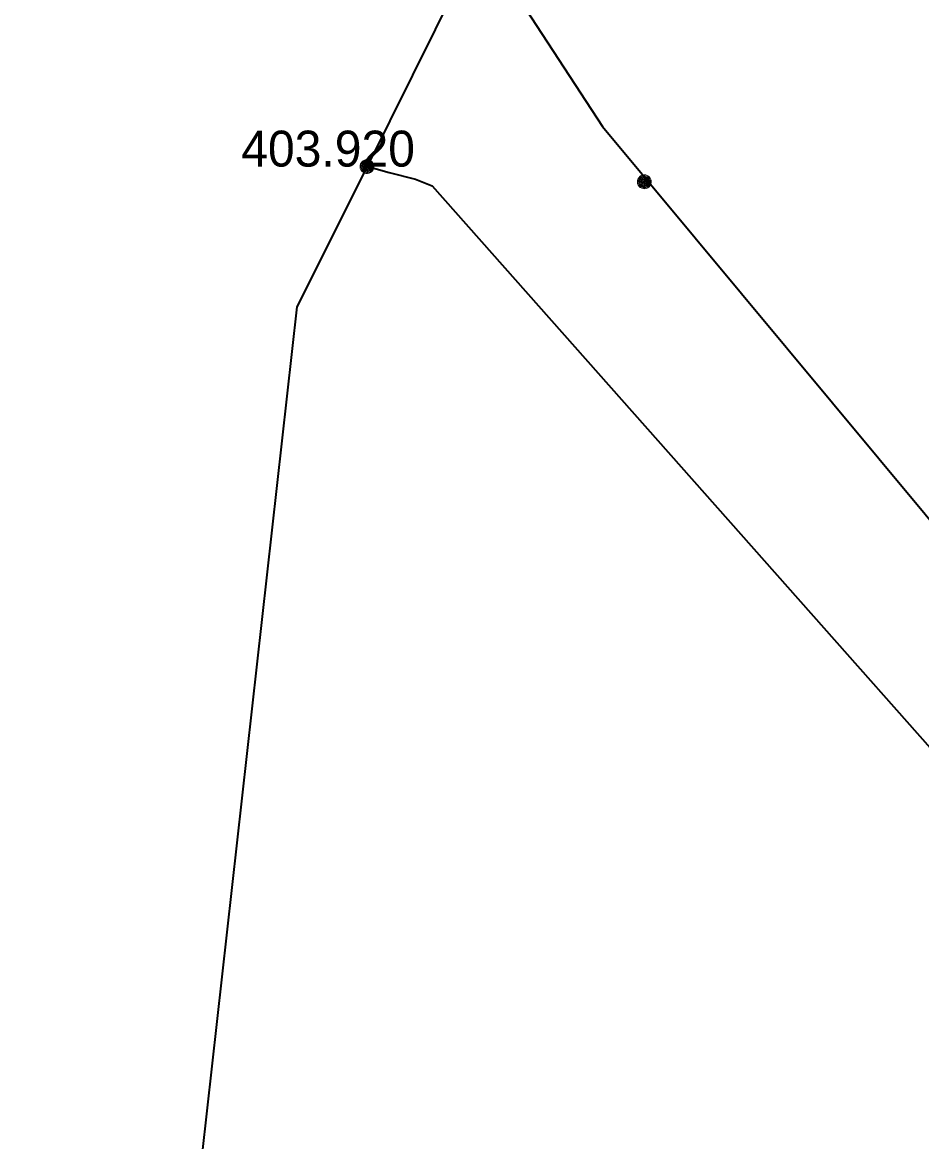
# Model space of a CAD drawing. Extents: x -873619 to -867639, y -1015082 to -1012326.
# Drawn here: x -867986.12 to -867956.09, y -1012758.26 to -1012720.88 of the extents above; entities that cross this region are included whole.
import ezdxf

# ---------------------------------------------------------------- set-up
doc = ezdxf.new("R2010")
doc.units = 0
doc.header["$LTSCALE"] = 0.44
for name, color, linetype, lineweight in [('1', 7, 'Continuous', 13), ('12', 7, 'Continuous', 13), ('21', 7, 'Continuous', 35), ('32', 7, 'Continuous', 13)]:
    doc.layers.add(name, color=color, linetype=linetype, lineweight=lineweight)

msp = doc.modelspace()

# ---------------------------------------------------------------- linework, layer by layer
at = {"layer": '1', "lineweight": 35}
for points in [[(-867928.158, -1012682.175), (-867928.532, -1012682.575), (-867928.834, -1012682.846), (-867929.235, -1012683.248), (-867941.259, -1012695.377), (-867959.972, -1012709.533), (-867967.543, -1012714.627), (-867970.064, -1012716.534), (-867974.611, -1012725.697)], [(-867974.611, -1012725.697), (-867976.949, -1012730.385), (-867980.624, -1012763.205), (-867983.112, -1012775.195), (-867978.719, -1012795.525), (-867979.823, -1012805.464), (-867997.768, -1012829.005), (-868011.042, -1012836.499), (-868058.95, -1012844.4), (-868077.43, -1012833.46), (-868085.171, -1012827.86)], [(-867974.611, -1012725.697), (-867974.301, -1012725.775), (-867973.868, -1012725.89), (-867972.988, -1012726.12), (-867972.44, -1012726.34), (-867942.73, -1012759.87), (-867932.66, -1012771.332), (-867928.969, -1012774.977), (-867916.529, -1012789.697), (-867904.95, -1012804.27)]]:
    msp.add_lwpolyline(points, dxfattribs=at)
at = {"layer": '1'}
for points in [[(-867974.38, -1012725.697), (-867974.386, -1012725.645), (-867974.403, -1012725.595), (-867974.432, -1012725.551), (-867974.469, -1012725.514), (-867974.514, -1012725.487), (-867974.564, -1012725.47), (-867974.617, -1012725.466), (-867974.669, -1012725.473), (-867974.718, -1012725.492), (-867974.761, -1012725.521), (-867974.797, -1012725.56), (-867974.823, -1012725.605), (-867974.839, -1012725.656), (-867974.842, -1012725.708), (-867974.834, -1012725.76), (-867974.814, -1012725.809), (-867974.783, -1012725.852), (-867974.744, -1012725.886), (-867974.698, -1012725.912), (-867974.647, -1012725.926), (-867974.594, -1012725.928), (-867974.543, -1012725.918), (-867974.495, -1012725.897), (-867974.452, -1012725.866), (-867974.418, -1012725.825), (-867974.394, -1012725.779), (-867974.382, -1012725.728)], [(-867974.41, -1012725.697), (-867974.416, -1012725.648), (-867974.433, -1012725.602), (-867974.461, -1012725.562), (-867974.498, -1012725.53), (-867974.542, -1012725.508), (-867974.59, -1012725.497), (-867974.639, -1012725.497), (-867974.686, -1012725.51), (-867974.729, -1012725.534), (-867974.765, -1012725.567), (-867974.792, -1012725.608), (-867974.808, -1012725.655), (-867974.812, -1012725.704), (-867974.805, -1012725.752), (-867974.786, -1012725.797), (-867974.756, -1012725.837), (-867974.718, -1012725.868), (-867974.674, -1012725.888), (-867974.626, -1012725.898), (-867974.577, -1012725.896), (-867974.53, -1012725.881), (-867974.487, -1012725.856), (-867974.453, -1012725.822), (-867974.427, -1012725.78), (-867974.413, -1012725.733)], [(-867974.44, -1012725.697), (-867974.446, -1012725.652), (-867974.463, -1012725.61), (-867974.491, -1012725.575), (-867974.527, -1012725.548), (-867974.569, -1012725.531), (-867974.614, -1012725.526), (-867974.659, -1012725.532), (-867974.7, -1012725.551), (-867974.735, -1012725.579), (-867974.762, -1012725.616), (-867974.778, -1012725.658), (-867974.782, -1012725.703), (-867974.775, -1012725.748), (-867974.756, -1012725.789), (-867974.727, -1012725.823), (-867974.69, -1012725.849), (-867974.647, -1012725.865), (-867974.602, -1012725.868), (-867974.557, -1012725.86), (-867974.517, -1012725.84), (-867974.483, -1012725.811), (-867974.457, -1012725.773), (-867974.443, -1012725.73)], [(-867974.47, -1012725.697), (-867974.475, -1012725.656), (-867974.493, -1012725.619), (-867974.52, -1012725.588), (-867974.555, -1012725.567), (-867974.595, -1012725.556), (-867974.636, -1012725.558), (-867974.675, -1012725.571), (-867974.709, -1012725.595), (-867974.734, -1012725.627), (-867974.749, -1012725.665), (-867974.752, -1012725.706), (-867974.744, -1012725.746), (-867974.724, -1012725.782), (-867974.695, -1012725.811), (-867974.658, -1012725.83), (-867974.618, -1012725.838), (-867974.577, -1012725.834), (-867974.539, -1012725.819), (-867974.507, -1012725.793), (-867974.484, -1012725.759), (-867974.471, -1012725.72)], [(-867974.5, -1012725.697), (-867974.505, -1012725.661), (-867974.523, -1012725.629), (-867974.549, -1012725.604), (-867974.583, -1012725.589), (-867974.619, -1012725.586), (-867974.654, -1012725.594), (-867974.685, -1012725.614), (-867974.708, -1012725.642), (-867974.721, -1012725.676), (-867974.721, -1012725.713), (-867974.71, -1012725.748), (-867974.689, -1012725.777), (-867974.659, -1012725.798), (-867974.624, -1012725.808), (-867974.587, -1012725.806), (-867974.553, -1012725.792), (-867974.526, -1012725.769), (-867974.507, -1012725.737), (-867974.5, -1012725.702)], [(-867974.53, -1012725.697), (-867974.535, -1012725.666), (-867974.552, -1012725.64), (-867974.578, -1012725.623), (-867974.608, -1012725.616), (-867974.639, -1012725.62), (-867974.666, -1012725.637), (-867974.684, -1012725.661), (-867974.692, -1012725.692), (-867974.688, -1012725.722), (-867974.673, -1012725.75), (-867974.649, -1012725.769), (-867974.619, -1012725.778), (-867974.588, -1012725.775), (-867974.56, -1012725.761), (-867974.54, -1012725.737), (-867974.53, -1012725.708)], [(-867974.56, -1012725.697), (-867974.565, -1012725.673), (-867974.582, -1012725.655), (-867974.605, -1012725.646), (-867974.629, -1012725.649), (-867974.65, -1012725.663), (-867974.661, -1012725.685), (-867974.661, -1012725.71), (-867974.649, -1012725.731), (-867974.629, -1012725.745), (-867974.604, -1012725.748), (-867974.581, -1012725.739), (-867974.565, -1012725.721)], [(-867974.59, -1012725.697), (-867974.595, -1012725.682), (-867974.61, -1012725.676), (-867974.625, -1012725.68), (-867974.632, -1012725.694), (-867974.628, -1012725.709), (-867974.615, -1012725.718), (-867974.6, -1012725.715), (-867974.59, -1012725.703)]]:
    msp.add_lwpolyline(points, close=True, dxfattribs=at)
at = {"layer": '12'}
for points in [[(-867974.38, -1012725.697), (-867974.386, -1012725.645), (-867974.403, -1012725.595), (-867974.432, -1012725.551), (-867974.469, -1012725.514), (-867974.514, -1012725.487), (-867974.564, -1012725.47), (-867974.617, -1012725.466), (-867974.669, -1012725.473), (-867974.718, -1012725.492), (-867974.761, -1012725.521), (-867974.797, -1012725.56), (-867974.823, -1012725.605), (-867974.839, -1012725.656), (-867974.842, -1012725.708), (-867974.834, -1012725.76), (-867974.814, -1012725.809), (-867974.783, -1012725.852), (-867974.744, -1012725.886), (-867974.698, -1012725.912), (-867974.647, -1012725.926), (-867974.594, -1012725.928), (-867974.543, -1012725.918), (-867974.495, -1012725.897), (-867974.452, -1012725.866), (-867974.418, -1012725.825), (-867974.394, -1012725.779), (-867974.382, -1012725.728)], [(-867974.41, -1012725.697), (-867974.416, -1012725.648), (-867974.433, -1012725.602), (-867974.461, -1012725.562), (-867974.498, -1012725.53), (-867974.542, -1012725.508), (-867974.59, -1012725.497), (-867974.639, -1012725.497), (-867974.686, -1012725.51), (-867974.729, -1012725.534), (-867974.765, -1012725.567), (-867974.792, -1012725.608), (-867974.808, -1012725.655), (-867974.812, -1012725.704), (-867974.805, -1012725.752), (-867974.786, -1012725.797), (-867974.756, -1012725.837), (-867974.718, -1012725.868), (-867974.674, -1012725.888), (-867974.626, -1012725.898), (-867974.577, -1012725.896), (-867974.53, -1012725.881), (-867974.487, -1012725.856), (-867974.453, -1012725.822), (-867974.427, -1012725.78), (-867974.413, -1012725.733)], [(-867974.44, -1012725.697), (-867974.446, -1012725.652), (-867974.463, -1012725.61), (-867974.491, -1012725.575), (-867974.527, -1012725.548), (-867974.569, -1012725.531), (-867974.614, -1012725.526), (-867974.659, -1012725.532), (-867974.7, -1012725.551), (-867974.735, -1012725.579), (-867974.762, -1012725.616), (-867974.778, -1012725.658), (-867974.782, -1012725.703), (-867974.775, -1012725.748), (-867974.756, -1012725.789), (-867974.727, -1012725.823), (-867974.69, -1012725.849), (-867974.647, -1012725.865), (-867974.602, -1012725.868), (-867974.557, -1012725.86), (-867974.517, -1012725.84), (-867974.483, -1012725.811), (-867974.457, -1012725.773), (-867974.443, -1012725.73)], [(-867974.47, -1012725.697), (-867974.475, -1012725.656), (-867974.493, -1012725.619), (-867974.52, -1012725.588), (-867974.555, -1012725.567), (-867974.595, -1012725.556), (-867974.636, -1012725.558), (-867974.675, -1012725.571), (-867974.709, -1012725.595), (-867974.734, -1012725.627), (-867974.749, -1012725.665), (-867974.752, -1012725.706), (-867974.744, -1012725.746), (-867974.724, -1012725.782), (-867974.695, -1012725.811), (-867974.658, -1012725.83), (-867974.618, -1012725.838), (-867974.577, -1012725.834), (-867974.539, -1012725.819), (-867974.507, -1012725.793), (-867974.484, -1012725.759), (-867974.471, -1012725.72)], [(-867974.5, -1012725.697), (-867974.505, -1012725.661), (-867974.523, -1012725.629), (-867974.549, -1012725.604), (-867974.583, -1012725.589), (-867974.619, -1012725.586), (-867974.654, -1012725.594), (-867974.685, -1012725.614), (-867974.708, -1012725.642), (-867974.721, -1012725.676), (-867974.721, -1012725.713), (-867974.71, -1012725.748), (-867974.689, -1012725.777), (-867974.659, -1012725.798), (-867974.624, -1012725.808), (-867974.587, -1012725.806), (-867974.553, -1012725.792), (-867974.526, -1012725.769), (-867974.507, -1012725.737), (-867974.5, -1012725.702)], [(-867974.53, -1012725.697), (-867974.535, -1012725.666), (-867974.552, -1012725.64), (-867974.578, -1012725.623), (-867974.608, -1012725.616), (-867974.639, -1012725.62), (-867974.666, -1012725.637), (-867974.684, -1012725.661), (-867974.692, -1012725.692), (-867974.688, -1012725.722), (-867974.673, -1012725.75), (-867974.649, -1012725.769), (-867974.619, -1012725.778), (-867974.588, -1012725.775), (-867974.56, -1012725.761), (-867974.54, -1012725.737), (-867974.53, -1012725.708)], [(-867974.56, -1012725.697), (-867974.565, -1012725.673), (-867974.582, -1012725.655), (-867974.605, -1012725.646), (-867974.629, -1012725.649), (-867974.65, -1012725.663), (-867974.661, -1012725.685), (-867974.661, -1012725.71), (-867974.649, -1012725.731), (-867974.629, -1012725.745), (-867974.604, -1012725.748), (-867974.581, -1012725.739), (-867974.565, -1012725.721)], [(-867974.59, -1012725.697), (-867974.595, -1012725.682), (-867974.61, -1012725.676), (-867974.625, -1012725.68), (-867974.632, -1012725.694), (-867974.628, -1012725.709), (-867974.615, -1012725.718), (-867974.6, -1012725.715), (-867974.59, -1012725.703)]]:
    msp.add_lwpolyline(points, close=True, dxfattribs=at)
at = {"layer": '21'}
msp.add_lwpolyline([(-867981.801, -1012701.313), (-867966.749, -1012724.362), (-867954.427, -1012739.171)], dxfattribs=at)
at = {"layer": '32'}
for points in [[(-867965.12, -1012726.205), (-867965.126, -1012726.153), (-867965.143, -1012726.103), (-867965.172, -1012726.059), (-867965.209, -1012726.022), (-867965.254, -1012725.995), (-867965.304, -1012725.978), (-867965.357, -1012725.974), (-867965.409, -1012725.981), (-867965.458, -1012726), (-867965.501, -1012726.029), (-867965.537, -1012726.068), (-867965.563, -1012726.113), (-867965.579, -1012726.164), (-867965.582, -1012726.216), (-867965.574, -1012726.268), (-867965.554, -1012726.317), (-867965.523, -1012726.36), (-867965.484, -1012726.394), (-867965.438, -1012726.42), (-867965.387, -1012726.434), (-867965.334, -1012726.436), (-867965.283, -1012726.426), (-867965.235, -1012726.405), (-867965.192, -1012726.374), (-867965.158, -1012726.333), (-867965.134, -1012726.287), (-867965.122, -1012726.236)], [(-867965.15, -1012726.205), (-867965.156, -1012726.156), (-867965.173, -1012726.11), (-867965.201, -1012726.07), (-867965.238, -1012726.038), (-867965.282, -1012726.016), (-867965.33, -1012726.005), (-867965.379, -1012726.005), (-867965.426, -1012726.018), (-867965.469, -1012726.042), (-867965.505, -1012726.075), (-867965.532, -1012726.116), (-867965.548, -1012726.163), (-867965.552, -1012726.212), (-867965.545, -1012726.26), (-867965.526, -1012726.305), (-867965.496, -1012726.345), (-867965.458, -1012726.376), (-867965.414, -1012726.396), (-867965.366, -1012726.406), (-867965.317, -1012726.404), (-867965.27, -1012726.389), (-867965.227, -1012726.364), (-867965.193, -1012726.33), (-867965.167, -1012726.288), (-867965.153, -1012726.241)], [(-867965.18, -1012726.205), (-867965.186, -1012726.16), (-867965.203, -1012726.118), (-867965.231, -1012726.083), (-867965.267, -1012726.056), (-867965.309, -1012726.039), (-867965.354, -1012726.034), (-867965.399, -1012726.04), (-867965.44, -1012726.059), (-867965.475, -1012726.087), (-867965.502, -1012726.124), (-867965.518, -1012726.166), (-867965.522, -1012726.211), (-867965.515, -1012726.256), (-867965.496, -1012726.297), (-867965.467, -1012726.331), (-867965.43, -1012726.357), (-867965.387, -1012726.373), (-867965.342, -1012726.376), (-867965.297, -1012726.368), (-867965.257, -1012726.348), (-867965.223, -1012726.319), (-867965.197, -1012726.281), (-867965.183, -1012726.238)], [(-867965.21, -1012726.205), (-867965.215, -1012726.164), (-867965.233, -1012726.127), (-867965.26, -1012726.096), (-867965.295, -1012726.075), (-867965.335, -1012726.064), (-867965.376, -1012726.066), (-867965.415, -1012726.079), (-867965.449, -1012726.103), (-867965.474, -1012726.135), (-867965.489, -1012726.173), (-867965.492, -1012726.214), (-867965.484, -1012726.254), (-867965.464, -1012726.29), (-867965.435, -1012726.319), (-867965.398, -1012726.338), (-867965.358, -1012726.346), (-867965.317, -1012726.342), (-867965.279, -1012726.327), (-867965.247, -1012726.301), (-867965.224, -1012726.267), (-867965.211, -1012726.228)], [(-867965.24, -1012726.205), (-867965.245, -1012726.169), (-867965.263, -1012726.137), (-867965.289, -1012726.112), (-867965.323, -1012726.097), (-867965.359, -1012726.094), (-867965.394, -1012726.102), (-867965.425, -1012726.122), (-867965.448, -1012726.15), (-867965.461, -1012726.184), (-867965.461, -1012726.221), (-867965.45, -1012726.256), (-867965.429, -1012726.285), (-867965.399, -1012726.306), (-867965.364, -1012726.316), (-867965.327, -1012726.314), (-867965.293, -1012726.3), (-867965.266, -1012726.277), (-867965.247, -1012726.245), (-867965.24, -1012726.21)], [(-867965.27, -1012726.205), (-867965.275, -1012726.174), (-867965.292, -1012726.148), (-867965.318, -1012726.131), (-867965.348, -1012726.124), (-867965.379, -1012726.128), (-867965.406, -1012726.145), (-867965.424, -1012726.169), (-867965.432, -1012726.2), (-867965.428, -1012726.23), (-867965.413, -1012726.258), (-867965.389, -1012726.277), (-867965.359, -1012726.286), (-867965.328, -1012726.283), (-867965.3, -1012726.269), (-867965.28, -1012726.245), (-867965.27, -1012726.216)], [(-867965.3, -1012726.205), (-867965.305, -1012726.181), (-867965.322, -1012726.163), (-867965.345, -1012726.154), (-867965.369, -1012726.157), (-867965.39, -1012726.171), (-867965.401, -1012726.193), (-867965.401, -1012726.218), (-867965.389, -1012726.239), (-867965.369, -1012726.253), (-867965.344, -1012726.256), (-867965.321, -1012726.247), (-867965.305, -1012726.229)], [(-867965.33, -1012726.205), (-867965.335, -1012726.19), (-867965.35, -1012726.184), (-867965.365, -1012726.188), (-867965.372, -1012726.202), (-867965.368, -1012726.217), (-867965.355, -1012726.226), (-867965.34, -1012726.223), (-867965.33, -1012726.211)]]:
    msp.add_lwpolyline(points, close=True, dxfattribs=at)

# ---------------------------------------------------------------- texts
at = {"layer": '1'}
msp.add_text('403.920 ', height=1.2, dxfattribs=at).set_placement((-867978.811, -1012725.697))

doc.saveas('drawing.dxf')
